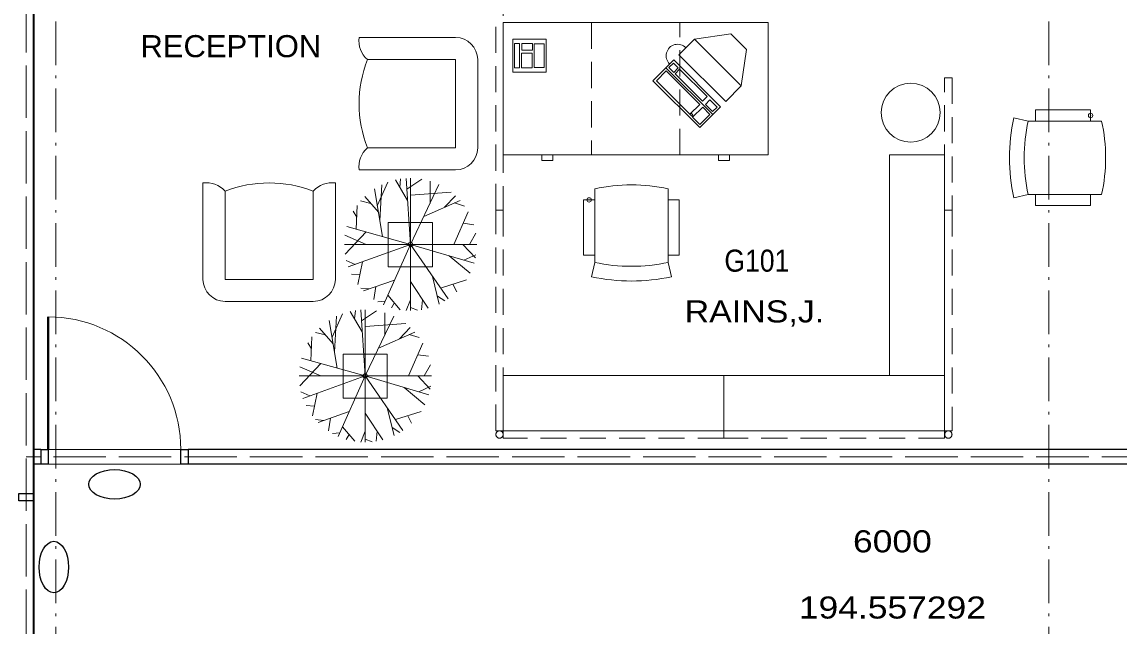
# Model space of a CAD drawing. Extents: x -118748 to -117136, y -118748 to -117596.
# Drawn here: x -118499.3 to -118260.7, y -118330.4 to -118199 of the extents above; entities that cross this region are included whole.
import ezdxf
from ezdxf.enums import TextEntityAlignment as Align

# ---------------------------------------------------------------- set-up
doc = ezdxf.new("R2010")
doc.units = 0
doc.header["$LTSCALE"] = 1.9
doc.header["$PDMODE"] = 32
doc.header["$PDSIZE"] = 0.95
for name, pattern in [('DOT_DASHED', [7.7, 5, -1.2, 0.3, -1.2]), ('LONG_DASHED', [7.5, 6, -1.5]), ('MEDIUM_DASHED', [4.5, 3, -1.5])]:
    doc.linetypes.add(name, pattern=pattern)
for name, color, linetype, lineweight in [('10', 7, 'DOT_DASHED', 13), ('15', 7, 'Continuous', 13), ('16', 7, 'Continuous', 13), ('20', 7, 'MEDIUM_DASHED', 13), ('23', 7, 'Continuous', 25), ('25', 7, 'Continuous', 13), ('26', 7, 'Continuous', 25), ('30', 7, 'Continuous', 13), ('4', 7, 'Continuous', 35), ('42', 7, 'Continuous', 25), ('45', 7, 'Continuous', 25), ('5', 7, 'Continuous', 13), ('6', 7, 'Continuous', 13), ('60', 7, 'LONG_DASHED', 13), ('9', 7, 'Continuous', 35)]:
    doc.layers.add(name, color=color, linetype=linetype, lineweight=lineweight)
doc.layers.add('53', color=7, linetype='Continuous')

msp = doc.modelspace()

# ---------------------------------------------------------------- linework, layer by layer
at = {"layer": '10'}
for p, q in [((-118491.921, -117628.339), (-118491.921, -118698.41)), ((-118275.921, -117628.339), (-118275.921, -118698.41))]:
    msp.add_line(p, q, dxfattribs=at)
at = {"layer": '15'}
for p, q in [((-118404.942, -118202.433), (-118425.928, -118202.433)), ((-118400.142, -118226.433), (-118400.142, -118207.233)), ((-118266.858, -118218.188), (-118278.858, -118218.188)), ((-118278.858, -118218.188), (-118278.858, -118220.588)), ((-118266.858, -118220.588), (-118266.858, -118218.188)), ((-118280.458, -118220.588), (-118283.586, -118219.912)), ((-118264.458, -118220.588), (-118280.458, -118220.588)), ((-118266.858, -118220.588), (-118278.858, -118220.588)), ((-118425.928, -118231.233), (-118404.942, -118231.233)), ((-118459.894, -118234.044), (-118459.894, -118255.029)), ((-118431.094, -118255.029), (-118431.094, -118234.044)), ((-118374.71, -118235.341), (-118374.71, -118251.341)), ((-118358.71, -118235.341), (-118358.71, -118251.341)), ((-118377.11, -118237.741), (-118377.11, -118249.741)), ((-118374.71, -118237.741), (-118377.11, -118237.741)), ((-118374.71, -118237.741), (-118374.71, -118249.741)), ((-118358.71, -118237.741), (-118358.71, -118249.741)), ((-118356.31, -118237.741), (-118358.71, -118237.741)), ((-118356.31, -118237.741), (-118356.31, -118249.741)), ((-118280.458, -118236.588), (-118283.586, -118237.264)), ((-118264.458, -118236.588), (-118280.458, -118236.588)), ((-118266.858, -118236.588), (-118278.858, -118236.588)), ((-118278.858, -118236.588), (-118278.858, -118238.988)), ((-118266.858, -118238.988), (-118266.858, -118236.588)), ((-118266.858, -118238.988), (-118278.858, -118238.988)), ((-118377.11, -118249.741), (-118374.71, -118249.741)), ((-118358.71, -118249.741), (-118356.31, -118249.741)), ((-118374.71, -118251.341), (-118375.386, -118254.469)), ((-118358.71, -118251.341), (-118358.034, -118254.469)), ((-118455.094, -118259.829), (-118435.894, -118259.829))]:
    msp.add_line(p, q, dxfattribs=at)
for points in [[(-118394.602, -118227.974), (-118394.602, -118199.174), (-118337.002, -118199.174), (-118337.002, -118227.974)], [(-118298.602, -118275.974), (-118310.602, -118275.974), (-118310.602, -118227.974), (-118298.602, -118227.974)], [(-118394.602, -118287.974), (-118394.602, -118275.974), (-118346.602, -118275.974), (-118346.602, -118287.974)], [(-118346.602, -118287.974), (-118346.602, -118275.974), (-118298.602, -118275.974), (-118298.602, -118287.974)]]:
    msp.add_lwpolyline(points, close=True, dxfattribs=at)
for points in [[(-118424.142, -118226.433), (-118404.942, -118226.433), (-118404.942, -118207.233), (-118424.142, -118207.233)], [(-118455.094, -118235.829), (-118455.094, -118255.029), (-118435.894, -118255.029), (-118435.894, -118235.829)]]:
    msp.add_lwpolyline(points, dxfattribs=at)
for centre, radius, start, end in [((-118420.451, -118203.128), 5.521, 172.77334, 228.03706), ((-118404.942, -118207.233), 4.8, 0, 90), ((-118399.229, -118216.833), 26.699, 158.92678, 201.07322), ((-118243.45, -118228.588), 41.063, 167.80217, 192.19783), ((-118243.45, -118228.588), 37.863, 167.80217, 192.19783), ((-118243.45, -118228.588), 37.863, 167.80217, 192.19783), ((-118301.467, -118228.588), 37.863, 347.80217, 12.19783), ((-118420.451, -118230.539), 5.521, 131.96294, 187.22666), ((-118404.942, -118226.433), 4.8, 270, 0), ((-118459.2, -118239.521), 5.521, 41.96294, 97.22666), ((-118445.494, -118260.743), 26.699, 68.92678, 111.07322), ((-118431.789, -118239.521), 5.521, 82.77334, 138.03706), ((-118366.71, -118272.349), 37.863, 77.80217, 102.19783), ((-118366.71, -118214.333), 37.863, 257.80217, 282.19783), ((-118366.71, -118214.333), 37.863, 257.80217, 282.19783), ((-118455.094, -118255.029), 4.8, 180, 270), ((-118435.894, -118255.029), 4.8, 270, 0), ((-118366.71, -118214.333), 41.063, 257.80217, 282.19783)]:
    msp.add_arc(centre, radius, start, end, dxfattribs=at)
for p in [(-118266.858, -118219.388), (-118375.91, -118237.741)]:
    msp.add_point(p, dxfattribs=at)
at = {"layer": '16'}
for p, q in [((-118353, -118202.781), (-118345.081, -118201.65)), ((-118345.081, -118201.65), (-118341.686, -118205.044)), ((-118342.818, -118212.964), (-118341.686, -118205.044)), ((-118359.223, -118209.004), (-118349.04, -118219.186))]:
    msp.add_line(p, q, dxfattribs=at)
for points in [[(-118392.492, -118209.99), (-118392.492, -118202.791), (-118385.292, -118202.791), (-118385.292, -118209.99)], [(-118356.394, -118206.176), (-118353, -118202.781), (-118342.818, -118212.964), (-118346.212, -118216.358)], [(-118391.035, -118208.984), (-118391.035, -118203.742), (-118392.117, -118203.742), (-118392.117, -118208.984)], [(-118390.536, -118203.742), (-118390.536, -118205.198), (-118388.248, -118205.198), (-118388.248, -118203.742)], [(-118387.873, -118203.825), (-118387.873, -118208.943), (-118385.668, -118208.943), (-118385.668, -118203.825)], [(-118390.619, -118205.864), (-118390.619, -118208.984), (-118388.331, -118208.984), (-118388.331, -118205.864)], [(-118362.051, -118211.832), (-118357.526, -118207.307), (-118347.343, -118217.489), (-118351.869, -118222.015)], [(-118359.139, -118209.685), (-118361.286, -118211.832), (-118353.99, -118219.129), (-118351.842, -118216.981)], [(-118358.55, -118208.979), (-118357.55, -118207.978), (-118356.52, -118209.008), (-118357.52, -118210.008)], [(-118357.226, -118210.303), (-118356.226, -118209.302), (-118350.254, -118215.275), (-118351.254, -118216.275)], [(-118350.607, -118216.981), (-118349.636, -118216.01), (-118348.106, -118217.54), (-118349.077, -118218.511)], [(-118353.99, -118219.129), (-118353.725, -118218.864), (-118353.343, -118219.246), (-118353.607, -118219.511)], [(-118351.224, -118217.599), (-118353.402, -118219.776), (-118351.813, -118221.365), (-118349.636, -118219.188)]]:
    msp.add_lwpolyline(points, close=True, dxfattribs=at)
msp.add_arc((-118356.668, -118206.389), 2.497, 44.02184, 225.97816, dxfattribs=at)
at = {"layer": '20'}
for points in [[(-118394.602, -118239.974), (-118396.202, -118239.974), (-118396.202, -118191.974), (-118394.602, -118191.974)], [(-118297.002, -118239.974), (-118298.602, -118239.974), (-118298.602, -118211.174), (-118297.002, -118211.174)], [(-118394.602, -118287.974), (-118396.202, -118287.974), (-118396.202, -118239.974), (-118394.602, -118239.974)], [(-118297.002, -118287.974), (-118298.602, -118287.974), (-118298.602, -118239.974), (-118297.002, -118239.974)], [(-118394.602, -118289.574), (-118394.602, -118287.974), (-118346.602, -118287.974), (-118346.602, -118289.574)], [(-118346.602, -118289.574), (-118346.602, -118287.974), (-118298.602, -118287.974), (-118298.602, -118289.574)]]:
    msp.add_lwpolyline(points, close=True, dxfattribs=at)
for centre in [(-118395.402, -118288.774), (-118297.802, -118288.774)]:
    msp.add_circle(centre, 0.8, dxfattribs=at)
at = {"layer": '23'}
for p, q in [((-118496.721, -118180.01), (-118496.721, -118292.01)), ((-118495.121, -118292.01), (-118496.721, -118292.01)), ((-118495.121, -118292.01), (-118495.121, -118295.21)), ((-118463.121, -118292.01), (-118463.121, -118295.21)), ((-118126.371, -118292.01), (-118463.121, -118292.01)), ((-118496.721, -118295.21), (-118496.721, -118301.61)), ((-118495.121, -118295.21), (-118496.721, -118295.21)), ((-118123.171, -118295.21), (-118463.121, -118295.21)), ((-118499.921, -118301.61), (-118496.721, -118301.61))]:
    msp.add_line(p, q, dxfattribs=at)
at = {"layer": '23', "linetype": 'MEDIUM_DASHED', "lineweight": 13}
for points in [[(-118394.602, -118227.974), (-118394.602, -118199.174), (-118375.402, -118199.174), (-118375.402, -118227.974)], [(-118356.202, -118227.974), (-118356.202, -118199.174), (-118337.002, -118199.174), (-118337.002, -118227.974)], [(-118386.202, -118227.974), (-118386.202, -118229.174), (-118383.802, -118229.174), (-118383.802, -118227.974)], [(-118347.802, -118227.974), (-118347.802, -118229.174), (-118345.402, -118229.174), (-118345.402, -118227.974)]]:
    msp.add_lwpolyline(points, close=True, dxfattribs=at)
at = {"layer": '25', "lineweight": 40}
msp.add_line((-118493.521, -118263.21), (-118493.521, -118292.01), dxfattribs=at)
at = {"layer": '25'}
msp.add_arc((-118493.521, -118292.01), 28.8, 0.00001, 90, dxfattribs=at)
at = {"layer": '26'}
for points in [[(-118495.121, -118292.01), (-118493.521, -118292.01), (-118493.521, -118295.21), (-118495.121, -118295.21)], [(-118463.121, -118295.21), (-118464.721, -118295.21), (-118464.721, -118292.01), (-118463.121, -118292.01)], [(-118496.721, -118301.61), (-118496.721, -118303.21), (-118499.921, -118303.21), (-118499.921, -118301.61)]]:
    msp.add_lwpolyline(points, dxfattribs=at)
at = {"layer": '30'}
for p, q in [((-118415.392, -118237.85), (-118418.032, -118233.416)), ((-118417.073, -118235.028), (-118416.9, -118233.198)), ((-118414.746, -118247.436), (-118415.714, -118233.069)), ((-118415.555, -118235.423), (-118412.285, -118233.248)), ((-118414.746, -118261.836), (-118414.746, -118233.036)), ((-118410.496, -118238.496), (-118410.499, -118233.677)), ((-118420.824, -118245.727), (-118422.595, -118235.363)), ((-118421.973, -118239.007), (-118419.709, -118233.918)), ((-118421.416, -118242.261), (-118420.999, -118234.464)), ((-118414.746, -118247.436), (-118408.564, -118234.431)), ((-118414.746, -118236.715), (-118405.951, -118236.035)), ((-118423.399, -118238.505), (-118425.606, -118237.979)), ((-118421.728, -118240.436), (-118424.686, -118237.017)), ((-118411.865, -118241.375), (-118403.978, -118237.876)), ((-118407.33, -118239.363), (-118404.964, -118236.869)), ((-118405.193, -118238.415), (-118403.021, -118239.077)), ((-118426.461, -118241.52), (-118427.203, -118240.211)), ((-118426.553, -118244.115), (-118426.37, -118238.936)), ((-118405.316, -118247.436), (-118402.221, -118240.331)), ((-118403.313, -118242.838), (-118400.995, -118243.164)), ((-118424.428, -118247.436), (-118429.006, -118245.435)), ((-118424.386, -118244.725), (-118428.986, -118249.579)), ((-118414.746, -118247.436), (-118428.608, -118243.537)), ((-118401.909, -118247.436), (-118400.554, -118244.998)), ((-118429.146, -118247.436), (-118400.346, -118247.436)), ((-118414.746, -118247.436), (-118428.293, -118252.32)), ((-118414.746, -118247.436), (-118420.648, -118260.571)), ((-118414.746, -118247.436), (-118400.938, -118251.522)), ((-118414.746, -118247.436), (-118406.566, -118259.287)), ((-118403.343, -118247.436), (-118400.643, -118250.344)), ((-118406.315, -118249.931), (-118401.781, -118253.702)), ((-118403.131, -118250.873), (-118400.523, -118249.688)), ((-118426.816, -118251.788), (-118428.725, -118250.895)), ((-118425.196, -118251.204), (-118426.231, -118256.123)), ((-118425.793, -118254.043), (-118427.626, -118253.876)), ((-118418.223, -118255.175), (-118425, -118257.547)), ((-118409.958, -118254.373), (-118408.496, -118260.409)), ((-118408.206, -118256.911), (-118402.596, -118255.165)), ((-118423.77, -118257.116), (-118425.57, -118256.934)), ((-118422.328, -118256.612), (-118422.75, -118259.407)), ((-118414.746, -118255.504), (-118410.954, -118261.328)), ((-118405.518, -118256.075), (-118404.689, -118257.742)), ((-118420.299, -118259.793), (-118421.883, -118259.943)), ((-118419.71, -118258.484), (-118417.027, -118261.655)), ((-118414.746, -118259.448), (-118415.683, -118261.806)), ((-118412.172, -118259.457), (-118412.35, -118261.635)), ((-118408.921, -118258.656), (-118407.259, -118259.737)), ((-118431.82, -118267.612), (-118429.557, -118262.524)), ((-118425.239, -118266.456), (-118427.88, -118262.022)), ((-118426.92, -118263.633), (-118426.748, -118261.804)), ((-118424.594, -118276.042), (-118425.561, -118261.674)), ((-118425.403, -118264.028), (-118422.133, -118261.854)), ((-118424.594, -118290.442), (-118424.594, -118261.642)), ((-118420.344, -118267.102), (-118420.346, -118262.283)), ((-118418.276, -118260.179), (-118418.907, -118261.222)), ((-118414.746, -118261.17), (-118413.231, -118261.756)), ((-118430.672, -118274.332), (-118432.443, -118263.969)), ((-118431.264, -118270.867), (-118430.846, -118263.07)), ((-118424.594, -118276.042), (-118418.411, -118263.037)), ((-118424.594, -118265.32), (-118415.798, -118264.64)), ((-118433.247, -118267.111), (-118435.453, -118266.585)), ((-118431.576, -118269.042), (-118434.534, -118265.623)), ((-118421.712, -118269.981), (-118413.825, -118266.482)), ((-118417.177, -118267.969), (-118414.811, -118265.475)), ((-118415.041, -118267.021), (-118412.869, -118267.682)), ((-118436.309, -118270.126), (-118437.05, -118268.817)), ((-118436.401, -118272.721), (-118436.217, -118267.542)), ((-118415.163, -118276.042), (-118412.069, -118268.937)), ((-118413.16, -118271.443), (-118410.842, -118271.769)), ((-118434.275, -118276.042), (-118438.854, -118274.04)), ((-118434.234, -118273.331), (-118438.833, -118278.185)), ((-118424.594, -118276.042), (-118438.456, -118272.143)), ((-118411.757, -118276.042), (-118410.402, -118273.604)), ((-118438.994, -118276.042), (-118410.194, -118276.042)), ((-118424.594, -118276.042), (-118438.14, -118280.926)), ((-118424.594, -118276.042), (-118430.496, -118289.177)), ((-118424.594, -118276.042), (-118410.786, -118280.128)), ((-118424.594, -118276.042), (-118416.414, -118287.893)), ((-118413.191, -118276.042), (-118410.49, -118278.95)), ((-118416.163, -118278.537), (-118411.628, -118282.307)), ((-118412.978, -118279.479), (-118410.371, -118278.293)), ((-118436.663, -118280.393), (-118438.572, -118279.501)), ((-118435.043, -118279.809), (-118436.079, -118284.728)), ((-118435.641, -118282.648), (-118437.474, -118282.482)), ((-118428.071, -118283.78), (-118434.847, -118286.152)), ((-118419.805, -118282.979), (-118418.344, -118289.015)), ((-118418.053, -118285.517), (-118412.444, -118283.77)), ((-118433.618, -118285.722), (-118435.418, -118285.539)), ((-118432.176, -118285.217), (-118432.598, -118288.012)), ((-118424.594, -118284.11), (-118420.802, -118289.934)), ((-118415.366, -118284.68), (-118414.536, -118286.347)), ((-118430.146, -118288.399), (-118431.731, -118288.549)), ((-118429.558, -118287.09), (-118426.874, -118290.26)), ((-118424.594, -118288.054), (-118425.53, -118290.411)), ((-118422.02, -118288.063), (-118422.198, -118290.241)), ((-118418.768, -118287.261), (-118417.107, -118288.342)), ((-118428.124, -118288.785), (-118428.754, -118289.828)), ((-118424.594, -118289.775), (-118423.079, -118290.362))]:
    msp.add_line(p, q, dxfattribs=at)
for points in [[(-118419.59, -118252.284), (-118419.59, -118242.684), (-118409.99, -118242.684), (-118409.99, -118252.284)], [(-118429.437, -118280.89), (-118429.437, -118271.29), (-118419.837, -118271.29), (-118419.837, -118280.89)]]:
    msp.add_lwpolyline(points, close=True, dxfattribs=at)
msp.add_circle((-118305.992, -118218.764), 6.4, dxfattribs=at)
for p in [(-118414.746, -118247.436), (-118424.594, -118276.042)]:
    msp.add_point(p, dxfattribs=at)
at = {"layer": '4'}
msp.add_lwpolyline([(-118496.721, -117964.01), (-118496.721, -118636.01), (-118271.121, -118636.01), (-118271.121, -118588.01), (-118115.969, -118588.01), (-118106.1, -118586.234), (-118096.66, -118581.314), (-118089.115, -118573.804), (-118084.156, -118564.399), (-118081.154, -118548.633), (-118079.134, -118548.633), (-117884.057, -118548.587), (-117881.646, -118565.336), (-117876.897, -118574.111), (-117869.271, -118581.538), (-117859.789, -118586.351), (-117850.271, -118588.01), (-117695.121, -118588.01), (-117695.121, -118636.01), (-117469.521, -118636.01), (-117469.521, -117964.01)], close=True, dxfattribs=at)
at = {"layer": '42'}
for centre, major_axis in [((-118479.121, -118299.61), (-5.6, 0)), ((-118492.321, -118317.61), (0, -5.6))]:
    msp.add_ellipse(centre, major_axis=major_axis, ratio=0.571429, dxfattribs=at)
at = {"layer": '5'}
for points in [[(-118115.969, -118588.01), (-118271.121, -118588.01), (-118271.121, -118636.01), (-118496.721, -118636.01), (-118496.721, -117964.01)], [(-118126.371, -118184.81), (-118126.371, -118292.01), (-118463.121, -118292.01), (-118496.721, -118292.01), (-118496.721, -118180.01), (-118496.721, -117964.01)], [(-118123.174, -118415.21), (-118123.175, -118343.21), (-118272.721, -118343.21), (-118496.721, -118343.21), (-118496.721, -118333.61), (-118496.721, -118301.61), (-118496.721, -118295.21), (-118463.121, -118295.21), (-118123.171, -118295.21), (-118123.171, -118184.81)]]:
    msp.add_lwpolyline(points, dxfattribs=at)
at = {"layer": '6'}
msp.add_lwpolyline([(-118126.371, -118184.81), (-118126.371, -118292.01), (-118496.721, -118292.01), (-118496.721, -117964.01)], dxfattribs=at)
msp.add_lwpolyline([(-118496.721, -118343.21), (-118123.171, -118343.21), (-118123.171, -118295.21), (-118496.721, -118295.21)], close=True, dxfattribs=at)
at = {"layer": '60'}
for p, q in [((-118498.321, -118180.01), (-118498.321, -118343.21)), ((-118124.771, -118293.61), (-118498.321, -118293.61))]:
    msp.add_line(p, q, dxfattribs=at)

# ---------------------------------------------------------------- texts
at = {"layer": '45', "width": 1.2}
for s, p in [('6000', (-118309.965, -118314.41)), ('194.557292', (-118309.965, -118328.81))]:
    msp.add_text(s, height=4.8, dxfattribs=at).set_placement(p, align=Align.CENTER)
at = {"layer": '53'}
for s, width, p in [('RECEPTION', 1.05, (-118473.487, -118206.704)), ('RAINS,J.', 1.15, (-118355.142, -118264.404))]:
    msp.add_text(s, height=4.8, dxfattribs=dict(at, width=width)).set_placement(p)
at = {"layer": '9', "width": 0.9}
msp.add_text('G101', height=4.8, dxfattribs=at).set_placement((-118339.44, -118253.361), align=Align.CENTER)

doc.saveas('drawing.dxf')
